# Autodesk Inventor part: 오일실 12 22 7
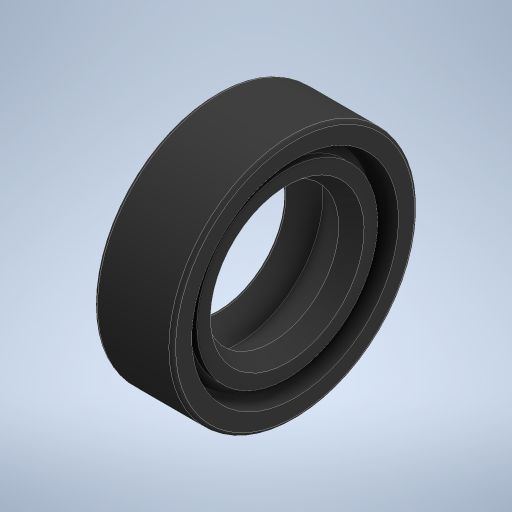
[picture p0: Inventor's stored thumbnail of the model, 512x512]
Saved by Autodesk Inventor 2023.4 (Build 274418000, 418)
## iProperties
Created: 2024-05
Part Number: 오일실 12 22 7
Material: 고무
Description: 오일-실
Document SubType Name: Modeling
Designer: user
Density: 0.93 g/cm^3
Appearance: 기본값
Author: jhkim
Sending System: Autodesk Inventor 2025
Preprocessor: ST-DEVELOPER v20
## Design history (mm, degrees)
feature "Solid1"
node "솔리드1"
